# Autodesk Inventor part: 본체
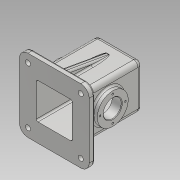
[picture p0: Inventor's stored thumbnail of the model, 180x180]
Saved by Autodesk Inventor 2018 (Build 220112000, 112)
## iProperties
Created: 2022-11
Part Number: 본체
Material: 알루미늄 6061
Document SubType Name: Modeling
Designer: home
Density: 2.7 g/cm^3
Appearance: 알루미늄 - 평지
Mass: 1267.49 g
Surface Area: 1004.35 cm^2
Volume: 469.441 cm^3
Author: home
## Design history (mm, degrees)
sketch "스케치1"
  geometry: L1 (62, -65)-(-62, -65); L2 (-62, -65)-(-62, 65); L3 (-62, 65)-(62, 65); L4 (62, 65)-(62, -65); 3 further points
  constraints: 8 end point, 2 midpoint, 2 parallel, 1 horizontal, 1 horizontal alignment, 1 perpendicular, 1 vertical alignment
  dimensions: "d0" = 124 distance of L1.start L1.end; "d1" = 130 distance of L3.end L1.start
extrude "돌출1" new body sketch "스케치1" distance "d2" = 10; taper "d3" = 0 deg
sketch "스케치2"
  geometry: L1 (-40, 40)-(40, 40); L2 (40, 40)-(40, -40); L3 (40, -40)-(-40, -40); L4 (-40, -40)-(-40, 40); 3 further points
  constraints: 8 end point, 2 midpoint, 2 parallel, 1 horizontal, 1 horizontal alignment, 1 perpendicular, 1 vertical alignment
  dimensions: "d4" = 80 distance of L1.start L1.end; "d5" = 80 distance of L3.end L1.start
extrude "돌출2" join sketch "스케치2" distance "d6" = 107; taper "d7" = 0 deg
sketch "스케치3"
  geometry: L1 (32, -32)-(-32, -32); L2 (-32, -32)-(-32, 32); L3 (-32, 32)-(32, 32); L4 (32, 32)-(32, -32); 3 further points
  constraints: 8 end point, 2 midpoint, 2 parallel, 1 horizontal, 1 horizontal alignment, 1 perpendicular, 1 vertical alignment
  dimensions: "d8" = 64 distance of L1.start L1.end; "d9" = 64 distance of L1.end L2.end
extrude "돌출3" cut sketch "스케치3" distance "d10" = 109; taper "d11" = 0 deg
sketch "스케치4"
  geometry: L1 (105, -10)-(-25, -10) reference; C1 r 27.5 at (40, 45); 2 further points
  constraints: 1 centre point, 1 midpoint, 1 vertical alignment
  dimensions: "d12" = 55 diameter of C1; "d13" = 55 distance from line of L1 C1.centre
extrude "돌출4" join sketch "스케치4" distance "d14" = 9; taper "d15" = 0 deg
sketch "스케치5"
  geometry: C1 r 27.5 at (0, 0) reference; 2 further points
  constraints: 1 coincident
hole "구멍1" sketch "스케치5" at (0, 0) diameter "d16" = 32; stored, may be unused: countersink angle "d20" = 90 deg, drill point angle "d22" = 0 deg; dims "d17" = 6, "d18" = 4, "d19" = 2, "d21" = 32
sketch "스케치6"
  geometry: C1 r 16 at (0, 0) reference; C2 r 27.5 at (0, 0) reference; A1 r 22.5 centre (0, 0) between (0, 22.5) and (-22.5, 0); 3 further points
  constraints: 4 point on circle, 2 horizontal alignment, 2 vertical alignment, 1 centre point, 1 coincident
  dimensions: "d23" = 45 diameter of A1
hole "구멍2" sketch "스케치6" at (0, 22.5), (-22.5, 0), (0, -22.5), (22.5, 0) diameter "d24" = 3.242; stored, may be unused: countersink angle "d28" = 90 deg, drill point angle "d30" = 118 deg; dims "d25" = 8, "d26" = 4, "d27" = 2, "d29" = 10
sketch "스케치7"
  geometry: C1 r 20 at (0, 0); 1 further point
  constraints: 1 centre point, 1 coincident
  dimensions: "d31" = 40 diameter of C1
extrude "돌출5" join sketch "스케치7" distance "d32" = 10; taper "d33" = -10 deg
sketch "스케치8"
  geometry: C1 r 18.237 at (0, 0) reference; 1 further point
  constraints: 1 coincident
hole "구멍3" sketch "스케치8" at (0, 0) diameter "d34" = 21; stored, may be unused: countersink angle "d38" = 90 deg, drill point angle "d40" = 0 deg; dims "d35" = 8, "d36" = 28, "d37" = 4, "d39" = 10
sketch "스케치9"
  geometry: L1 (10, -40)-(117, -40) reference; L2 (95.069, -40)-(10, -55); L3 (10, 65)-(10, -65) reference; L4 (95.069, -40)-(10, -40); L5 (10, -40)-(10, -55); L6 (0, -65)-(10, -65) reference; 1 further point
  constraints: 6 end point, 2 point on line, 1 horizontal, 1 perpendicular
  dimensions: "d41" = 100 deg angle of L2 L3; "d42" = 10 distance from line of L2.end L6
extrude "돌출6" join sketch "스케치9" stored distance "d43" = 10; taper "d44" = 0 deg
fillet "모깎기1" dims "d45" = 8
fillet "모깎기2" dims "d46" = 3
fillet "모깎기3" dims "d47" = 15
fillet "모깎기4" dims "d48" = 3
fillet "모깎기5" dims "d49" = 3
sketch "스케치10"
  geometry: L1 (4.737, -2.252)-(59.263, -2.252); L2 (59.263, -2.252)-(59.263, -11.748); L3 (59.263, -11.748)-(4.737, -11.748); L4 (4.737, -11.748)-(4.737, -2.252); L5 (13.763, 18)-(50.237, 18) reference; L6 (72, -96)-(72, 0) reference; 4 further points
  constraints: 2 midpoint, 1 horizontal alignment, 1 vertical alignment, 2 other
  dimensions: "d51" = 25 distance from line of L5 point (32, -7); "d52" = 40 distance from line of L6 point (32, -7)
feature "엠보싱1" sketch "스케치10" dims "d0" = 124, "d1" = 130, "d53" = 0.5, "d54" = 0
sketch "스케치11"
  geometry: A1 r 15 centre (-47, 50) between (-47, 65) and (-62, 50) reference; A2 r 15 centre (-47, -50) between (-62, -50) and (-47, -65) reference; A3 r 15 centre (47, -50) between (47, -65) and (62, -50) reference; A4 r 15 centre (47, 50) between (62, 50) and (47, 65) reference; 5 further points
  constraints: 4 coincident
hole "구멍4" sketch "스케치11" at (47, 50), (-47, 50), (-47, -50), (47, -50) diameter "d55" = 9; stored, may be unused: countersink angle "d59" = 90 deg, drill point angle "d61" = 0 deg; dims "d56" = 8, "d57" = 28, "d58" = 4, "d60" = 10
chamfer "모따기1" distance "d62" = 1; stored, may be unused: second distance "d63" = 2, angle "d64" = 45 deg
node "솔리드1"
mirror "미러1"
mirror "미러2"
